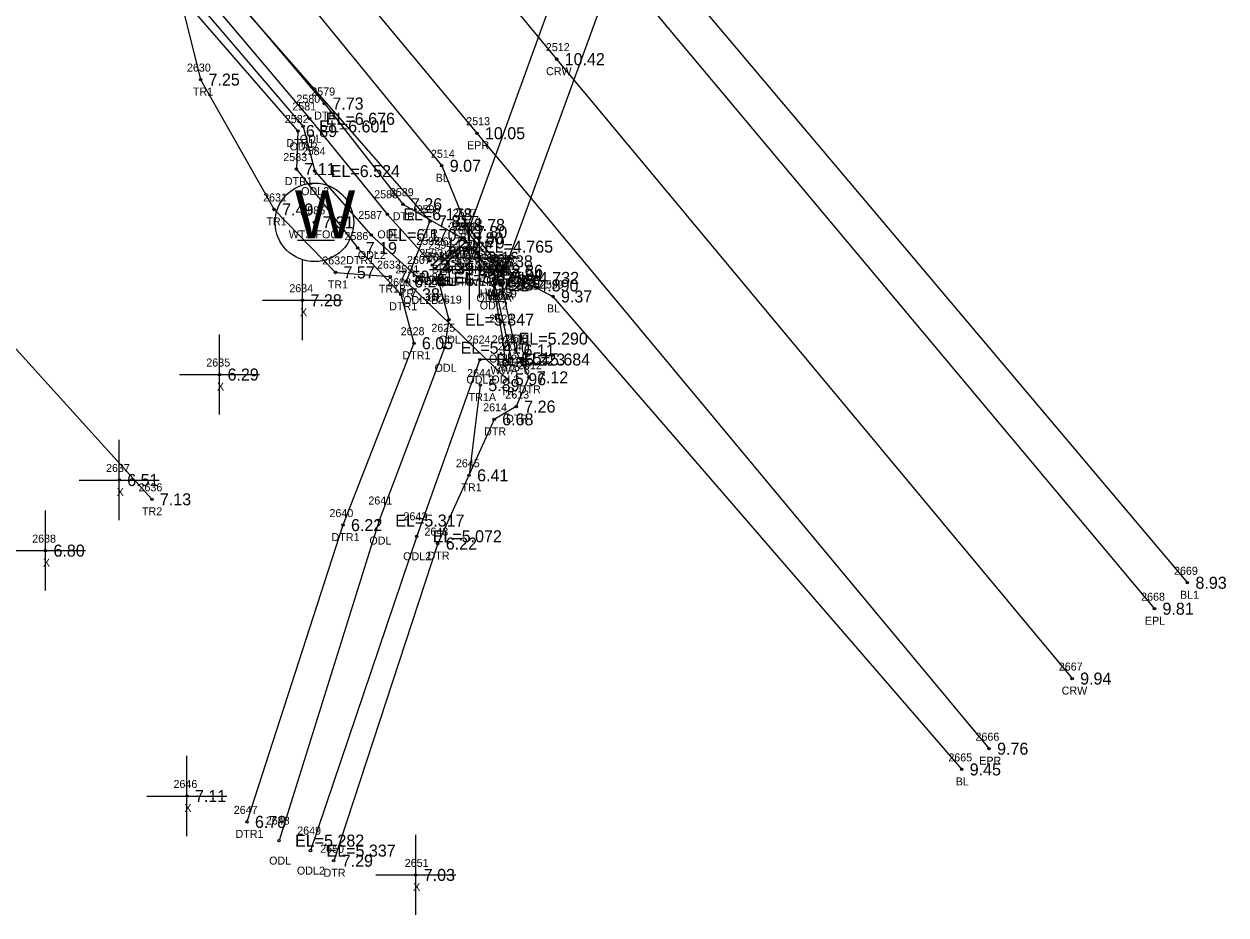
# Model space of a CAD drawing. Extents: x 2042211 to 2045853, y 303080 to 309569.
# Drawn here: x 2044641.9 to 2044792.1, y 304311.6 to 304422.9 of the extents above; entities that cross this region are included whole.
import ezdxf

# ---------------------------------------------------------------- set-up
doc = ezdxf.new("R2010")
doc.units = 0
for name, color, linetype in [('BR_500YR_SCOUR', 7, 'Continuous'), ('RD_DTM_BkLn1', 7, 'Continuous'), ('RD_DTM_BkLn_txCode', 7, 'Continuous'), ('RD_EX_Bridge_txCode', 7, 'Continuous'), ('RD_EX_H2O', 7, 'Continuous'), ('RD_EX_H2O_txCode', 7, 'Continuous'), ('RD_EX_Misc', 7, 'Continuous'), ('RD_EX_Misc_txCode', 7, 'Continuous'), ('RD_EX_Road', 7, 'Continuous'), ('RD_EX_Road_txCode', 7, 'Continuous'), ('RD_EX_TX_Bridge_ELEV', 7, 'Continuous'), ('RD_EX_TX_H2O_ELEV', 7, 'Continuous'), ('RD_EX_TX_Misc_ELEV', 7, 'Continuous'), ('RD_EX_TX_Road_ELEV', 7, 'Continuous'), ('RD_EX_TX_UT_ELEV', 7, 'Continuous'), ('RD_EX_TX_VEG_ELEV', 7, 'Continuous'), ('RD_EX_UT_txCode', 7, 'Continuous'), ('RD_EX_VEG_txCode', 7, 'Continuous'), ('RD_HC_Survey_ELEV', 7, 'Continuous'), ('RD_HC_Survey_txCode', 7, 'Continuous'), ('RD_SMD_Locator', 7, 'Continuous')]:
    doc.layers.add(name, color=color, linetype=linetype)

msp = doc.modelspace()

# ---------------------------------------------------------------- linework, layer by layer
at = {"layer": 'BR_500YR_SCOUR'}
for p, q in [((2044676.02, 304395.92), (2044680.65, 304395.92)), ((2044697.02, 304395.62), (2044693.19, 304392.37)), ((2044701.32, 304390.75), (2044696.86, 304396.13)), ((2044698.88, 304377.8), (2044697.48, 304366.53))]:
    msp.add_line(p, q, dxfattribs=at)
for points in [[(2044509.17, 304539.98), (2044524.22, 304524.97), (2044542.12, 304505.8), (2044583.21, 304448.88), (2044599.3, 304426.6), (2044609.14, 304424.55), (2044616.83, 304408.81), (2044657.84, 304363.53)], [(2044646.25, 304451.16), (2044692.59, 304398.27), (2044689.62, 304390.75), (2044702.2, 304378.53)], [(2044714.68, 304444.82), (2044719.12, 304439.4), (2044701.71, 304391.61), (2044697.34, 304396.91), (2044714.68, 304444.82)], [(2044660.66, 304429.06), (2044663.92, 304415.97), (2044673.11, 304399.74), (2044680.78, 304391.87), (2044687.63, 304391.35)], [(2044702.76, 304381.14), (2044700.68, 304390.38), (2044700.86, 304390.87)]]:
    msp.add_lwpolyline(points, dxfattribs=at)
for centre, radius in [((2044663.92, 304415.97), 0.15), ((2044678.15, 304398.13), 4.91), ((2044673.11, 304399.74), 0.15), ((2044678.15, 304398.13), 0.15), ((2044692.59, 304398.27), 0.15), ((2044697.34, 304396.91), 0.15), ((2044696.86, 304396.13), 0.15), ((2044697.02, 304395.62), 0.15), ((2044693.19, 304392.37), 0.15), ((2044680.78, 304391.87), 0.15), ((2044687.63, 304391.35), 0.15), ((2044689.62, 304390.75), 0.15), ((2044700.86, 304390.87), 0.15), ((2044701.32, 304390.75), 0.15), ((2044701.71, 304391.61), 0.15), ((2044700.68, 304390.38), 0.15), ((2044702.76, 304381.14), 0.15), ((2044702.2, 304378.53), 0.15), ((2044698.88, 304377.8), 0.15), ((2044697.48, 304366.53), 0.15), ((2044657.84, 304363.53), 0.15)]:
    msp.add_circle(centre, radius, dxfattribs=at)
at = {"layer": 'RD_DTM_BkLn1'}
msp.add_line((2044701.47, 304390.48), (2044703.28, 304382.13), dxfattribs=at)
for points in [[(2043528.91, 305830.2), (2043556.35, 305797.19), (2043619.96, 305720.85), (2043684.02, 305644.21), (2043747.98, 305567.9), (2043812.35, 305491.13), (2043876, 305414.64), (2043940.22, 305337.83), (2044003.86, 305261.82), (2044067.88, 305184.94), (2044131, 305108.73), (2044195.62, 305032.03), (2044259.59, 304955.88), (2044323.63, 304879.52), (2044387.48, 304802.4), (2044451.92, 304725.21), (2044515.94, 304648.42), (2044581.15, 304571.52), (2044645.01, 304495.17), (2044708.42, 304418.52), (2044772.84, 304341.13)], [(2043798.36, 305479.17), (2043862.32, 305402.71), (2043926.37, 305326.69), (2043989.74, 305249.79), (2043988.33, 305246.75), (2043991.19, 305243.51), (2043994.75, 305243.65), (2044053.09, 305173.37), (2044116.28, 305094.9), (2044180.2, 305019.52), (2044245.63, 304943.51), (2044308.37, 304866.05), (2044373.1, 304789.96), (2044438.35, 304712.62), (2044501.57, 304636.05), (2044528.47, 304600.32), (2044565.87, 304558.85), (2044630.47, 304482.97), (2044694.06, 304405.2), (2044697.06, 304397.81), (2044701.81, 304392.08), (2044707.96, 304388.87), (2044759.04, 304329.78)], [(2044398.41, 304821.04), (2044402.86, 304816.02), (2044414.62, 304801.81), (2044465.4, 304737.7), (2044530.97, 304661.39), (2044596.61, 304584.37), (2044660.09, 304507.62), (2044710.08, 304447.81), (2044714.26, 304444.21), (2044718.28, 304439), (2044721.7, 304430.82), (2044787.25, 304353.1)], [(2044692.88, 304392.81), (2044694.03, 304393.83), (2044696.61, 304396.14)]]:
    msp.add_lwpolyline(points, dxfattribs=at)
at = {"layer": 'RD_EX_H2O'}
for points in [[(2044526.69, 304588.12), (2044529.75, 304589.5), (2044560.23, 304553.15), (2044624.26, 304478.07), (2044679.39, 304412.98), (2044689.21, 304400.4), (2044696.61, 304396.14)], [(2044526.69, 304588.12), (2044524.46, 304585.8), (2044557.52, 304549.44), (2044620.27, 304473.78), (2044676.08, 304409.54), (2044675.89, 304404.78), (2044683.56, 304394.92), (2044688.93, 304389.15), (2044690.58, 304383.03), (2044681.72, 304360.31), (2044669.72, 304323.23)], [(2044528.02, 304587.51), (2044559.1, 304551.6), (2044622.39, 304476.37), (2044677.57, 304411.07), (2044687.25, 304399.14), (2044692.5, 304393.31)], [(2044526.69, 304586.11), (2044558.35, 304550.68), (2044621.04, 304475.29), (2044676.74, 304410.12), (2044678.19, 304404.53), (2044685.26, 304396.55), (2044691.41, 304390.93)], [(2044697.33, 304395.1), (2044694.8, 304393.26), (2044693.54, 304391.23), (2044694.95, 304385.98), (2044694.42, 304382.46), (2044686.26, 304360.88), (2044673.73, 304320.89)], [(2044700.58, 304391.19), (2044700.5, 304390.25), (2044701.67, 304383.61), (2044701.96, 304381), (2044698.84, 304380.99), (2044690.93, 304358.91), (2044677.66, 304319.64)], [(2044703.28, 304382.13), (2044704.96, 304378.77), (2044703.37, 304375.12), (2044700.61, 304373.52), (2044693.56, 304358), (2044680.56, 304318.37)]]:
    msp.add_lwpolyline(points, dxfattribs=at)
at = {"layer": 'RD_EX_Misc'}
for p, q in [((2044698.79, 304388.71), (2044698.79, 304398.71)), ((2044697.53, 304387.24), (2044697.53, 304397.24)), ((2044693.79, 304393.71), (2044703.79, 304393.71)), ((2044676.66, 304383.4), (2044676.66, 304393.4)), ((2044692.53, 304392.24), (2044702.53, 304392.24)), ((2044671.66, 304388.4), (2044681.66, 304388.4)), ((2044666.29, 304374.12), (2044666.29, 304384.12)), ((2044661.29, 304379.12), (2044671.29, 304379.12)), ((2044653.76, 304360.94), (2044653.76, 304370.94)), ((2044648.76, 304365.94), (2044658.76, 304365.94)), ((2044644.54, 304352.12), (2044644.54, 304362.12)), ((2044639.54, 304357.12), (2044649.54, 304357.12)), ((2044662.22, 304321.46), (2044662.22, 304331.46)), ((2044657.22, 304326.46), (2044667.22, 304326.46)), ((2044690.81, 304311.6), (2044690.81, 304321.6)), ((2044685.81, 304316.6), (2044695.81, 304316.6))]:
    msp.add_line(p, q, dxfattribs=at)
at = {"layer": 'RD_EX_Road'}
for points in [[(2043522.11, 305820), (2043547.67, 305789.85), (2043610.72, 305713.32), (2043674.95, 305636.32), (2043738.18, 305559.62), (2043802.42, 305482.71), (2043865.72, 305405.84), (2043929.53, 305328.85), (2043994.13, 305253.28), (2044057.4, 305176.5), (2044121.27, 305100.2), (2044185.29, 305023.54), (2044249.56, 304947.28), (2044313.31, 304870.31), (2044377.09, 304793.29), (2044442, 304716.26), (2044505.92, 304639.55), (2044570.44, 304562.35), (2044634.61, 304485.93), (2044698.46, 304409.27), (2044762.46, 304332.37)], [(2044013.41, 305270.34), (2044077.97, 305194.15), (2044141.4, 305117.67), (2044205.92, 305040.83), (2044269.54, 304964.65), (2044331.73, 304891.04), (2044335.22, 304889.2), (2044346.01, 304875.31), (2044356.18, 304867.61), (2044370.01, 304868.14), (2044386.83, 304866.36), (2044389.44, 304849.53), (2044390.71, 304830.73), (2044393.77, 304818.44), (2044395.5, 304814.18), (2044398.16, 304811.09), (2044461.8, 304734.03), (2044526.04, 304657.6), (2044591.28, 304580.23), (2044655.29, 304503.62), (2044718.26, 304427.32), (2044783.13, 304349.86)]]:
    msp.add_lwpolyline(points, dxfattribs=at)
at = {"layer": 'RD_SMD_Locator'}
for centre in [(2044708.42, 304418.52), (2044679.39, 304412.98), (2044676.74, 304410.12), (2044677.57, 304411.07), (2044676.08, 304409.54), (2044698.46, 304409.27), (2044675.89, 304404.78), (2044678.19, 304404.53), (2044694.06, 304405.2), (2044689.21, 304400.4), (2044687.25, 304399.14), (2044685.26, 304396.55), (2044697.06, 304397.81), (2044696.61, 304396.14), (2044696.61, 304396.14), (2044697.33, 304395.1), (2044683.56, 304394.92), (2044694.03, 304393.83), (2044698.79, 304393.71), (2044692.5, 304393.31), (2044692.88, 304392.81), (2044694.8, 304393.26), (2044697.53, 304392.24), (2044701.81, 304392.08), (2044691.41, 304390.93), (2044693.54, 304391.23), (2044700.58, 304391.19), (2044701.47, 304390.48), (2044688.93, 304389.15), (2044700.5, 304390.25), (2044676.66, 304388.4), (2044707.96, 304388.87), (2044694.95, 304385.98), (2044690.58, 304383.03), (2044701.67, 304383.61), (2044694.42, 304382.46), (2044703.28, 304382.13), (2044703.28, 304382.13), (2044698.84, 304380.99), (2044701.96, 304381), (2044666.29, 304379.12), (2044704.96, 304378.77), (2044703.37, 304375.12), (2044700.61, 304373.52), (2044653.76, 304365.94), (2044686.26, 304360.88), (2044681.72, 304360.31), (2044690.93, 304358.91), (2044693.56, 304358), (2044644.54, 304357.12), (2044787.25, 304353.1), (2044783.13, 304349.86), (2044772.84, 304341.13), (2044762.46, 304332.37), (2044759.04, 304329.78), (2044662.22, 304326.46), (2044669.72, 304323.23), (2044673.73, 304320.89), (2044677.66, 304319.64), (2044680.56, 304318.37), (2044690.81, 304316.6)]:
    msp.add_circle(centre, 0.15, dxfattribs=at)

# ---------------------------------------------------------------- texts
at = {"layer": 'BR_500YR_SCOUR'}
for s, height, p in [('W', 6, (2044675.69, 304396.13)), ('BL2', 1, (2044692.82, 304391.83)), ('2609', 1, (2044699.78, 304391.48)), ('BL', 1, (2044701.05, 304390.08)), ('BL2B', 1, (2044701.61, 304380.13))]:
    msp.add_text(s, height=height, dxfattribs=at).set_placement(p)
at = {"layer": 'RD_DTM_BkLn_txCode'}
for s, p in [('2514', (2044692.71, 304406.2)), ('BL', (2044693.3, 304403.2)), ('2597', (2044695.43, 304398.81)), ('2595', (2044694.98, 304397.14)), ('BL', (2044696.3, 304395.81)), ('2594', (2044692.4, 304394.83)), ('BL2B', (2044694.94, 304394.14)), ('2593', (2044691.25, 304393.81)), ('2598', (2044700.18, 304393.08)), ('BL2A', (2044691.18, 304390.81)), ('2599', (2044706.33, 304389.87)), ('BL2A', (2044699.78, 304388.48)), ('BL', (2044707.21, 304386.87)), ('2610', (2044701.87, 304383.13)), ('2669', (2044785.57, 304354.1)), ('BL1', (2044786.32, 304351.1)), ('2665', (2044757.37, 304330.78)), ('BL', (2044758.29, 304327.78))]:
    msp.add_text(s, height=1, dxfattribs=at).set_placement(p)
at = {"layer": 'RD_EX_Bridge_txCode'}
for s, p in [('2601', (2044695.45, 304397.13)), ('2577', (2044695.71, 304397.91)), ('2602', (2044695.33, 304396.62)), ('HWB', (2044695.57, 304394.13)), ('CVL', (2044696.1, 304394.91)), ('2603', (2044691.49, 304393.37)), ('WWA .6', (2044694.42, 304393.62)), ('2576', (2044700.06, 304392.61)), ('2605', (2044698.98, 304391.38)), ('2606', (2044699.14, 304391.87)), ('2600', (2044699.59, 304391.75)), ('WWB', (2044691.81, 304390.37)), ('CVL', (2044700.47, 304389.61)), ('HWA .9', (2044698.83, 304388.75)), ('WWB', (2044699.48, 304388.87)), ('WW', (2044699.77, 304388.38)), ('2604', (2044701.07, 304382.14)), ('WWA .6', (2044700.16, 304379.14))]:
    msp.add_text(s, height=1, dxfattribs=at).set_placement(p)
at = {"layer": 'RD_EX_H2O_txCode'}
for s, p in [('2579', (2044677.76, 304413.98)), ('2580', (2044675.9, 304413.07)), ('2581', (2044675.39, 304412.12)), ('DTR', (2044678.12, 304410.98)), ('2582', (2044674.45, 304410.54)), ('ODL', (2044676.32, 304408.07)), ('DTR1', (2044674.65, 304407.54)), ('ODL2', (2044675.05, 304407.12)), ('2584', (2044676.56, 304406.53)), ('2583', (2044674.26, 304405.78)), ('DTR1', (2044674.45, 304402.78)), ('ODL2', (2044676.49, 304401.53)), ('2588', (2044685.62, 304401.14)), ('2589', (2044687.58, 304401.4)), ('2587', (2044683.63, 304398.55)), ('DTR', (2044687.94, 304398.4)), ('2596', (2044694.96, 304397.14)), ('2586', (2044681.91, 304395.92)), ('ODL', (2044686.01, 304396.14)), ('2616', (2044695.94, 304397.1)), ('2592', (2044690.87, 304395.31)), ('2617', (2044693.42, 304395.26)), ('DTRB', (2044694.87, 304394.14)), ('DTR1', (2044682.13, 304392.92)), ('ODL2', (2044683.57, 304393.55)), ('2607', (2044689.72, 304392.93)), ('2618', (2044692.17, 304393.23)), ('2620', (2044698.89, 304393.19)), ('ODLA', (2044695.6, 304392.1)), ('2621', (2044699.13, 304392.25)), ('2608', (2044687.24, 304390.15)), ('ODLB', (2044690.78, 304390.31)), ('ODL', (2044693.55, 304390.26)), ('ODL', (2044692.3, 304388.23)), ('ODL2A', (2044698.4, 304388.19)), ('DTR1', (2044687.5, 304387.15)), ('ODL2B', (2044689.25, 304387.93)), ('2619', (2044693.58, 304387.98)), ('ODL2', (2044698.81, 304387.25)), ('2622', (2044700.01, 304385.61)), ('2628', (2044688.93, 304384.03)), ('2625', (2044692.76, 304384.46)), ('ODL', (2044693.7, 304382.98)), ('2624', (2044697.18, 304382.99)), ('2623', (2044700.3, 304383)), ('2611', (2044702.2, 304383.13)), ('DTR1', (2044689.15, 304381.03)), ('ODL2', (2044699.97, 304380.61)), ('ODL', (2044693.17, 304379.46)), ('DTRA', (2044701.53, 304380.13)), ('2612', (2044703.59, 304379.77)), ('ODL2', (2044697.14, 304377.99)), ('ODL2', (2044700.26, 304378)), ('2613', (2044702, 304376.12)), ('DTR', (2044703.69, 304376.77)), ('2614', (2044699.24, 304374.52)), ('DTR', (2044702.1, 304373.12)), ('DTR', (2044699.35, 304371.52)), ('2641', (2044684.89, 304362.88)), ('2640', (2044680.03, 304361.31)), ('2642', (2044689.28, 304360.91)), ('DTR1', (2044680.29, 304358.31)), ('2643', (2044691.9, 304359)), ('ODL', (2044685.02, 304357.88)), ('ODL2', (2044689.24, 304355.91)), ('DTR', (2044692.29, 304356)), ('2647', (2044668.07, 304324.23)), ('2648', (2044672.08, 304322.89)), ('DTR1', (2044668.29, 304321.23)), ('2649', (2044676, 304321.64)), ('2650', (2044678.87, 304319.37)), ('ODL', (2044672.49, 304317.89)), ('ODL2', (2044675.96, 304316.64)), ('DTR', (2044679.29, 304316.37))]:
    msp.add_text(s, height=1, dxfattribs=at).set_placement(p)
at = {"layer": 'RD_EX_Misc_txCode'}
for s, p in [('2627', (2044697.14, 304394.71)), ('2626', (2044695.85, 304393.24)), ('MSP INVERT', (2044694.47, 304391.71)), ('MSP INVERT', (2044693.2, 304390.24)), ('2634', (2044675.01, 304389.4)), ('X', (2044676.35, 304386.4)), ('2635', (2044664.64, 304380.12)), ('X', (2044665.97, 304377.12)), ('2637', (2044652.11, 304366.94)), ('X', (2044653.45, 304363.94)), ('2638', (2044642.88, 304358.12)), ('X', (2044644.22, 304355.12)), ('2646', (2044660.54, 304327.46)), ('X', (2044661.9, 304324.46)), ('2651', (2044689.44, 304317.6)), ('X', (2044690.49, 304314.6))]:
    msp.add_text(s, height=1, dxfattribs=at).set_placement(p)
at = {"layer": 'RD_EX_Road_txCode'}
for s, p in [('2513', (2044697.12, 304410.27)), ('EPR', (2044697.23, 304407.27)), ('2668', (2044781.46, 304350.86)), ('EPL', (2044781.93, 304347.86)), ('2666', (2044760.76, 304333.37)), ('EPR', (2044761.23, 304330.37))]:
    msp.add_text(s, height=1, dxfattribs=at).set_placement(p)
at = {"layer": 'RD_EX_TX_Bridge_ELEV'}
for s, p in [('8.80', (2044697.86, 304395.38)), ('7.80', (2044698.34, 304396.16)), ('7.79', (2044698.02, 304394.87)), ('4.39', (2044694.19, 304391.62)), ('7.84', (2044702.71, 304390.86)), ('7.83', (2044701.68, 304389.63)), ('7.85', (2044701.86, 304390.12)), ('8.81', (2044702.32, 304390)), ('4.51', (2044703.76, 304380.39))]:
    msp.add_text(s, height=1.5, dxfattribs=at).set_placement(p)
at = {"layer": 'RD_EX_TX_H2O_ELEV'}
for s, p in [('7.73', (2044680.39, 304412.23)), ('EL=6.676', (2044679.57, 304410.32)), ('6.89', (2044677.08, 304408.79)), ('EL=6.601', (2044678.74, 304409.37)), ('7.11', (2044676.89, 304404.03)), ('EL=6.524', (2044680.19, 304403.78)), ('7.26', (2044690.21, 304399.65)), ('EL=6.178', (2044689.25, 304398.39)), ('EL=6.170', (2044687.26, 304395.8)), ('7.46', (2044697.61, 304395.39)), ('7.19', (2044684.56, 304394.17)), ('EL=4.765', (2044699.33, 304394.35)), ('EL=5.688', (2044694.5, 304392.56)), ('EL=5.188', (2044696.8, 304392.51)), ('EL=5.723', (2044693.41, 304390.18)), ('EL=5.625', (2044695.54, 304390.48)), ('EL=4.890', (2044702.5, 304389.5)), ('EL=4.732', (2044702.58, 304390.44)), ('7.38', (2044689.93, 304388.4)), ('EL=5.347', (2044696.95, 304385.23)), ('6.05', (2044691.58, 304382.28)), ('EL=5.410', (2044696.42, 304381.71)), ('EL=5.290', (2044703.67, 304382.86)), ('EL=5.223', (2044700.84, 304380.24)), ('EL=5.684', (2044703.96, 304380.25)), ('6.11', (2044704.28, 304381.38)), ('7.12', (2044705.96, 304378.02)), ('7.26', (2044704.37, 304374.37)), ('6.68', (2044701.61, 304372.77)), ('6.22', (2044682.72, 304359.56)), ('EL=5.317', (2044688.26, 304360.13)), ('EL=5.072', (2044692.93, 304358.16)), ('6.22', (2044694.56, 304357.25)), ('6.78', (2044670.72, 304322.48)), ('EL=5.282', (2044675.73, 304320.14)), ('EL=5.337', (2044679.66, 304318.89)), ('7.29', (2044681.56, 304317.62))]:
    msp.add_text(s, height=1.5, dxfattribs=at).set_placement(p)
at = {"layer": 'RD_EX_TX_Misc_ELEV'}
for s, p in [('9.07', (2044695.06, 304404.45)), ('8.78', (2044698.06, 304397.06)), ('7.46', (2044697.61, 304395.39)), ('5.54', (2044695.03, 304393.08)), ('2.16', (2044699.79, 304392.96)), ('5.51', (2044693.88, 304392.06)), ('2.22', (2044698.53, 304391.49)), ('8.86', (2044702.81, 304391.33)), ('8.09', (2044702.47, 304389.73)), ('7.28', (2044677.66, 304387.65)), ('9.37', (2044708.96, 304388.12)), ('6.11', (2044704.28, 304381.38)), ('6.29', (2044667.29, 304378.37)), ('6.51', (2044654.76, 304365.19)), ('6.80', (2044645.54, 304356.37)), ('8.93', (2044788.25, 304352.35)), ('9.45', (2044760.04, 304329.03)), ('7.11', (2044663.22, 304325.71)), ('7.03', (2044691.81, 304315.85))]:
    msp.add_text(s, height=1.5, dxfattribs=at).set_placement(p)
at = {"layer": 'RD_EX_TX_Road_ELEV'}
for s, p in [('10.05', (2044699.46, 304408.52)), ('9.81', (2044784.13, 304349.11)), ('9.76', (2044763.46, 304331.62))]:
    msp.add_text(s, height=1.5, dxfattribs=at).set_placement(p)
at = {"layer": 'RD_EX_TX_UT_ELEV'}
msp.add_text('7.31', height=1.5, dxfattribs=at).set_placement((2044679.15, 304397.38))
at = {"layer": 'RD_EX_TX_VEG_ELEV'}
for s, p in [('7.25', (2044664.92, 304415.22)), ('7.49', (2044674.11, 304398.99)), ('7.81', (2044693.59, 304397.52)), ('7.57', (2044681.78, 304391.12)), ('7.59', (2044688.63, 304390.6)), ('6.24', (2044690.62, 304390)), ('5.96', (2044703.2, 304377.78)), ('5.89', (2044699.88, 304377.05)), ('6.41', (2044698.48, 304365.78)), ('7.13', (2044658.84, 304362.78))]:
    msp.add_text(s, height=1.5, dxfattribs=at).set_placement(p)
at = {"layer": 'RD_EX_UT_txCode'}
for s, p in [('2585', (2044676.52, 304399.13)), ('WTS FOC', (2044674.94, 304396.13))]:
    msp.add_text(s, height=1, dxfattribs=at).set_placement(p)
at = {"layer": 'RD_EX_VEG_txCode'}
for s, p in [('2630', (2044662.22, 304416.97)), ('TR1', (2044662.96, 304413.97)), ('2631', (2044671.74, 304400.74)), ('2590', (2044690.92, 304399.27)), ('TR1', (2044672.15, 304397.74)), ('TR', (2044691.79, 304396.27)), ('2632', (2044679.13, 304392.87)), ('2633', (2044685.97, 304392.35)), ('2591', (2044688.27, 304391.75)), ('TR1', (2044679.82, 304389.87)), ('TR1B', (2044686.19, 304389.35)), ('TR', (2044688.82, 304388.75)), ('2615', (2044700.83, 304379.53)), ('2644', (2044697.23, 304378.8)), ('TR', (2044701.41, 304376.53)), ('TR1A', (2044697.43, 304375.8)), ('2645', (2044695.83, 304367.53)), ('2636', (2044656.17, 304364.53)), ('TR1', (2044696.52, 304364.53)), ('TR2', (2044656.6, 304361.53))]:
    msp.add_text(s, height=1, dxfattribs=at).set_placement(p)
at = {"layer": 'RD_HC_Survey_ELEV'}
for s, p in [('10.42', (2044709.42, 304417.77)), ('9.94', (2044773.84, 304340.38))]:
    msp.add_text(s, height=1.5, dxfattribs=at).set_placement(p)
at = {"layer": 'RD_HC_Survey_txCode'}
for s, p in [('2512', (2044707.07, 304419.52)), ('CRW', (2044707.1, 304416.52)), ('2667', (2044771.17, 304342.13)), ('CRW', (2044771.53, 304339.13))]:
    msp.add_text(s, height=1, dxfattribs=at).set_placement(p)

doc.saveas('drawing.dxf')
